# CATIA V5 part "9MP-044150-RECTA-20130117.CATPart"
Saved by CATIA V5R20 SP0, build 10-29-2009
Part number: 9MP-044150-RECTA-20130117
Revision: ANY
Definition: UNKNOWN
Nomenclature: 9MP-044150-RECTA-20130117
Source: Unknown
Bounding box of the stored display mesh (mm): x -188.627 to -38.627, y 1497.206 to 1501.206, z 0 to 4
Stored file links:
  C:\Users\Utente\Desktop\IO LAVORO\3D X SITO CF\CUMSA\3D files PF\PF 044150\9MP-044150-RECTA-20130117.CATPart
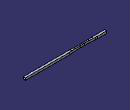
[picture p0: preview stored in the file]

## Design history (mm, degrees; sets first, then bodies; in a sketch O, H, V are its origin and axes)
Body1 "Cortar-Extruir1" (main body)
  Solid1: solid without history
